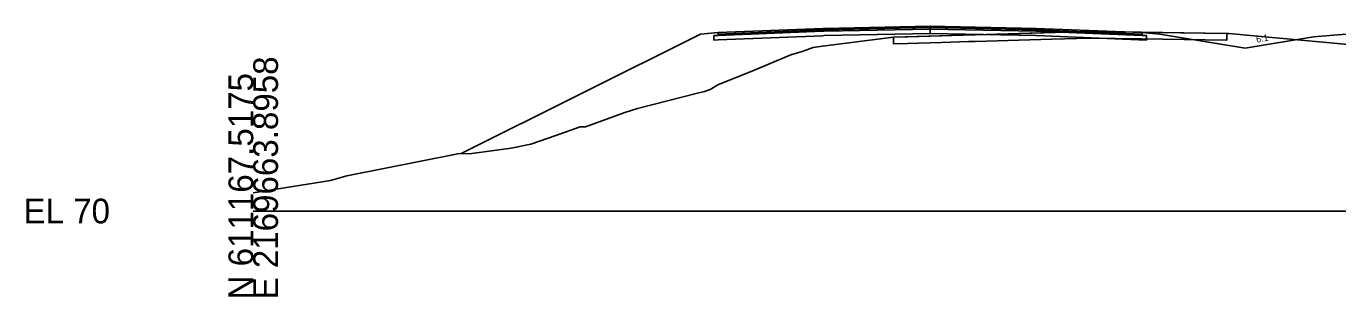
# Model space of a CAD drawing. Extents: x -26 to 1303, y -3010 to 12033.
# Drawn here: x 974.3 to 1122.8, y 5990.3 to 6020.9 of the extents above; entities that cross this region are included whole.
import ezdxf

# ---------------------------------------------------------------- set-up
doc = ezdxf.new("R2010")
doc.units = 0
for name, color, linetype in [('RD_GPK_XS_Cell', 7, 'Continuous'), ('RD_XS_Base', 7, 'Continuous'), ('RD_XS_ExGround', 7, 'Continuous'), ('RD_XS_ExPaveRet', 7, 'Continuous'), ('RD_XS_Greenside', 7, 'Continuous'), ('RD_XS_Pave', 7, 'Continuous'), ('RD_XS_PaveOvlay_CP', 7, 'Continuous'), ('RD_XS_TieSlope', 7, 'Continuous'), ('RD_XS_TX_Slope', 7, 'Continuous')]:
    doc.layers.add(name, color=color, linetype=linetype)

msp = doc.modelspace()

# ---------------------------------------------------------------- linework, layer by layer
at = {"layer": 'RD_GPK_XS_Cell'}
msp.add_line((1000, 6000), (1150, 6000), dxfattribs=at)
at = {"layer": 'RD_XS_Base'}
for p, q in [((1052.12, 6019.84), (1052.61, 6019.86)), ((1052.12, 6019.83), (1052.12, 6019.84)), ((1052.12, 6019.34), (1052.12, 6019.83)), ((1052.61, 6019.36), (1052.12, 6019.34)), ((1052.61, 6019.86), (1052.62, 6019.86)), ((1052.62, 6019.36), (1052.61, 6019.36)), ((1052.62, 6019.86), (1064.47, 6020.33)), ((1064.47, 6019.83), (1052.62, 6019.36)), ((1064.47, 6020.33), (1064.62, 6020.34)), ((1064.62, 6019.84), (1064.47, 6019.83)), ((1064.62, 6020.34), (1076.6, 6020.58)), ((1076.6, 6020.08), (1064.62, 6019.84)), ((1076.6, 6020.58), (1076.62, 6020.58)), ((1076.62, 6020.08), (1076.6, 6020.08)), ((1076.62, 6020.58), (1076.62, 6020.74)), ((1076.62, 6020.74), (1076.62, 6020.74)), ((1076.62, 6020.74), (1076.62, 6020.74)), ((1076.62, 6020.74), (1076.62, 6020.08)), ((1076.62, 6020.58), (1076.62, 6020.74)), ((1076.62, 6020.74), (1076.62, 6020.08)), ((1076.62, 6020.58), (1076.62, 6020.58)), ((1076.62, 6020.58), (1076.62, 6020.08)), ((1076.65, 6020.58), (1076.62, 6020.58)), ((1076.62, 6020.58), (1076.62, 6020.08)), ((1088.62, 6020.34), (1076.62, 6020.58)), ((1076.62, 6020.58), (1076.62, 6020.58)), ((1076.62, 6020.08), (1076.65, 6020.08)), ((1076.62, 6020.08), (1076.62, 6020.08)), ((1076.62, 6020.08), (1076.62, 6020.08)), ((1076.62, 6020.08), (1088.62, 6019.84)), ((1100.62, 6019.86), (1088.62, 6020.34)), ((1088.62, 6019.84), (1101.12, 6019.34)), ((1090.62, 6020.26), (1090.62, 6020.26)), ((1090.62, 6019.76), (1090.62, 6019.76)), ((1101.12, 6019.84), (1100.62, 6019.86)), ((1100.62, 6019.86), (1100.62, 6019.86)), ((1101.12, 6019.34), (1101.12, 6019.84)), ((1101.12, 6019.84), (1101.12, 6019.84)), ((1101.12, 6019.34), (1101.12, 6019.34)), ((1101.12, 6019.34), (1101.12, 6019.34))]:
    msp.add_line(p, q, dxfattribs=at)
at = {"layer": 'RD_XS_ExGround'}
msp.add_lwpolyline([(1000, 6002.05), (1008.76, 6003.47), (1010.61, 6003.99), (1023.16, 6006.48), (1024.75, 6006.52), (1029.19, 6007.11), (1031.43, 6007.56), (1034.26, 6008.56), (1037.02, 6009.51), (1037.62, 6009.51), (1042.06, 6011.15), (1043.48, 6011.61), (1050.29, 6013.32), (1051.09, 6013.52), (1051.71, 6013.76), (1052.57, 6014.26), (1056.63, 6015.9), (1060.85, 6017.65), (1062.12, 6018.06), (1063.37, 6018.49), (1064.43, 6018.64), (1072.46, 6019.66), (1081.72, 6019.93), (1094.66, 6020.31), (1110.16, 6020.09), (1110.21, 6020.09), (1110.26, 6020.09), (1110.42, 6020.07), (1126.8, 6018.57)], dxfattribs=at)
at = {"layer": 'RD_XS_ExPaveRet'}
for points in [[(1074.06, 6019.71), (1072.46, 6019.66), (1072.46, 6019.1), (1072.46, 6018.91), (1074.06, 6018.96), (1077.91, 6019.07), (1080.94, 6019.16), (1081.72, 6019.18), (1090.37, 6019.43), (1094.66, 6019.56), (1100.53, 6019.48), (1110.16, 6019.34), (1110.21, 6019.34), (1110.21, 6019.34), (1110.21, 6019.34), (1110.21, 6019.34), (1110.21, 6019.34), (1110.21, 6020), (1110.21, 6020.09), (1110.21, 6020.09), (1110.21, 6020.09), (1110.21, 6020.09), (1110.21, 6020.09), (1110.16, 6020.09), (1100.53, 6020.23), (1094.66, 6020.31), (1090.37, 6020.18), (1081.72, 6019.93), (1080.94, 6019.91), (1077.91, 6019.82), (1074.06, 6019.71)], [(1074.06, 6019.71), (1072.46, 6019.66), (1072.46, 6019.1), (1072.46, 6018.91), (1074.06, 6018.96), (1077.91, 6019.07), (1080.94, 6019.16), (1081.72, 6019.18), (1090.37, 6019.43), (1094.66, 6019.56), (1100.53, 6019.48), (1110.16, 6019.34), (1110.21, 6019.34), (1110.21, 6019.34), (1110.21, 6019.34), (1110.21, 6019.34), (1110.21, 6020), (1110.21, 6020.09), (1110.21, 6020.09), (1110.21, 6020.09), (1110.21, 6020.09), (1110.16, 6020.09), (1100.53, 6020.23), (1094.66, 6020.31), (1090.37, 6020.18), (1081.72, 6019.93), (1080.94, 6019.91), (1077.91, 6019.82), (1074.06, 6019.71)]]:
    msp.add_lwpolyline(points, dxfattribs=at)
at = {"layer": 'RD_XS_Greenside'}
for p, q in [((1050.62, 6020.02), (1023.55, 6006.49)), ((1102.62, 6020.02), (1112.27, 6018.41)), ((1120, 6019.7), (1112.27, 6018.41))]:
    msp.add_line(p, q, dxfattribs=at)
at = {"layer": 'RD_XS_Pave'}
for p, q in [((1076.6, 6020.9), (1064.62, 6020.66)), ((1076.62, 6020.9), (1076.6, 6020.9)), ((1076.65, 6020.9), (1076.62, 6020.9)), ((1088.62, 6020.66), (1076.62, 6020.9)), ((1064.47, 6020.65), (1052.62, 6020.18)), ((1064.47, 6020.49), (1052.62, 6020.02)), ((1052.62, 6020.02), (1064.47, 6020.49)), ((1052.62, 6019.86), (1064.47, 6020.33)), ((1052.62, 6020.18), (1052.62, 6020.17)), ((1052.62, 6020.17), (1052.62, 6020.02)), ((1052.62, 6020.02), (1052.62, 6020.02)), ((1052.62, 6020.02), (1052.62, 6019.86)), ((1064.62, 6020.66), (1064.47, 6020.65)), ((1064.62, 6020.5), (1064.47, 6020.49)), ((1064.47, 6020.49), (1064.62, 6020.5)), ((1064.47, 6020.33), (1064.62, 6020.34)), ((1076.6, 6020.74), (1064.62, 6020.5)), ((1064.62, 6020.5), (1076.6, 6020.74)), ((1064.62, 6020.34), (1076.6, 6020.58)), ((1076.62, 6020.74), (1076.6, 6020.74)), ((1076.6, 6020.74), (1076.62, 6020.74)), ((1076.6, 6020.58), (1076.62, 6020.58)), ((1076.62, 6020.58), (1076.62, 6020.74)), ((1076.62, 6020.74), (1076.62, 6020.74)), ((1076.62, 6020.74), (1076.65, 6020.74)), ((1076.65, 6020.74), (1076.62, 6020.74)), ((1076.62, 6020.74), (1076.62, 6020.74)), ((1076.62, 6020.74), (1076.62, 6020.58)), ((1076.62, 6020.58), (1076.62, 6020.74)), ((1076.62, 6020.74), (1088.62, 6020.5)), ((1088.62, 6020.5), (1076.62, 6020.74)), ((1076.62, 6020.74), (1076.62, 6020.58)), ((1076.62, 6020.58), (1076.65, 6020.58)), ((1076.62, 6020.58), (1076.62, 6020.58)), ((1076.62, 6020.58), (1076.62, 6020.58)), ((1076.62, 6020.58), (1088.62, 6020.34)), ((1100.62, 6020.18), (1088.62, 6020.66)), ((1088.62, 6020.5), (1100.62, 6020.02)), ((1100.62, 6020.02), (1088.62, 6020.5)), ((1088.62, 6020.34), (1100.62, 6019.86)), ((1090.62, 6020.58), (1090.62, 6020.58)), ((1090.62, 6020.42), (1090.62, 6020.42)), ((1090.62, 6020.42), (1090.62, 6020.42)), ((1090.62, 6020.26), (1090.62, 6020.26)), ((1100.62, 6020.02), (1100.62, 6020.18)), ((1100.62, 6020.18), (1100.62, 6020.18)), ((1100.62, 6020.02), (1100.62, 6020.02)), ((1100.62, 6020.02), (1100.62, 6020.02)), ((1100.62, 6019.86), (1100.62, 6020.02)), ((1100.62, 6020.02), (1100.62, 6020.02)), ((1100.62, 6019.86), (1100.62, 6019.86)), ((1100.62, 6019.86), (1100.62, 6019.86))]:
    msp.add_line(p, q, dxfattribs=at)
at = {"layer": 'RD_XS_PaveOvlay_CP'}
for p, q in [((1064.62, 6020.66), (1076.62, 6020.9)), ((1076.62, 6020.9), (1088.62, 6020.66)), ((1052.62, 6020.18), (1064.62, 6020.66)), ((1088.62, 6020.66), (1100.62, 6020.18))]:
    msp.add_line(p, q, dxfattribs=at)
at = {"layer": 'RD_XS_TieSlope'}
for p, q in [((1052.62, 6020.18), (1050.62, 6020.02)), ((1100.62, 6020.18), (1102.62, 6020.02)), ((1126, 6020.18), (1120, 6019.7))]:
    msp.add_line(p, q, dxfattribs=at)

# ---------------------------------------------------------------- texts
at = {"layer": 'RD_GPK_XS_Cell'}
for s, p in [('E 2169663.8958', (1002.8, 5990)), ('N 611167.5175', (1000, 5990))]:
    msp.add_text(s, height=2.8, rotation=90, dxfattribs=at).set_placement(p)
msp.add_text('EL 70', height=2.8, dxfattribs=at).set_placement((974, 5998.6))
at = {"layer": 'RD_XS_TX_Slope'}
msp.add_text('6:1', height=0.75, rotation=9.4642, dxfattribs=at).set_placement((1113.57, 6019.04))

doc.saveas('drawing.dxf')
